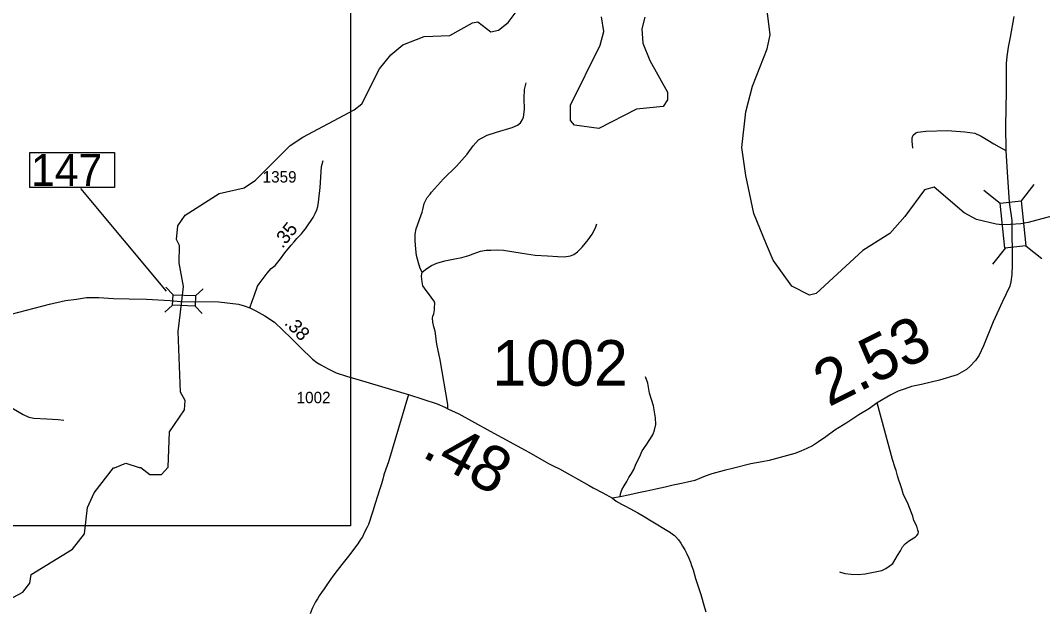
# Model space of a CAD drawing. Extents: x 2290615 to 2522933, y 819489 to 1012715.
# Drawn here: x 2317110 to 2328328, y 910143 to 916604 of the extents above; entities that cross this region are included whole.
import ezdxf

# ---------------------------------------------------------------- set-up
doc = ezdxf.new("R2010")
doc.units = 0
for name, color, linetype in [('Exist Hydrographic Creek Single Shore', 7, 'Continuous'), ('Exist Road Non-System Type 51', 7, 'Continuous'), ('Exist Road Secondary Mileage Hundredths English Label', 7, 'Continuous'), ('Exist Road Secondary Structure Standard Bridge CELL', 7, 'Continuous'), ('Exist Road Secondary Structure Standard Bridge Number Label', 7, 'Continuous'), ('Exist Road Secondary Type 51 Attributed', 7, 'Continuous'), ('Exist Road Secondary Type 51 Number Label', 7, 'Continuous'), ('Map Preparation Inset Cut Line', 7, 'Continuous')]:
    doc.layers.add(name, color=color, linetype=linetype)

msp = doc.modelspace()

# ---------------------------------------------------------------- linework, layer by layer
at = {"layer": 'Exist Hydrographic Creek Single Shore'}
for points in [[(2318130, 911698), (2318143, 911698), (2318265, 911748), (2318413, 911701), (2318430, 911701), (2318531, 911624), (2318656, 911626), (2318730, 911704), (2318745, 912092), (2318909, 912335), (2318916, 912437), (2318865, 912527), (2318841, 913193), (2318879, 913525), (2318898, 913685), (2318850, 913945), (2318856, 914135), (2318822, 914203), (2318837, 914351), (2318919, 914469), (2319292, 914705), (2319566, 914768), (2319690, 914852), (2320069, 915232), (2320210, 915323), (2320773, 915622), (2320855, 915688), (2321051, 916073), (2321174, 916226), (2321307, 916336), (2321539, 916428), (2321822, 916440), (2322070, 916578), (2322128, 916587), (2322271, 916478), (2322355, 916498), (2322462, 916581), (2322593, 916757)], [(2329032, 914619), (2328169, 914387), (2328089, 914375), (2327977, 914366), (2327884, 914361), (2327818, 914369), (2327601, 914419), (2327467, 914495), (2327139, 914774), (2327030, 914747), (2326817, 914452), (2326653, 914268), (2326354, 914082), (2325842, 913611), (2325769, 913592), (2325575, 913689), (2325372, 913973), (2325296, 914147), (2325159, 914486), (2325071, 914902), (2325027, 915209), (2325071, 915602), (2325143, 915884), (2325306, 916294), (2325337, 916446), (2325301, 916743)], [(2323961, 916639), (2323929, 916513), (2323939, 916356), (2324016, 916166), (2324211, 915816), (2324212, 915734), (2324163, 915659), (2323872, 915631), (2323457, 915417), (2323190, 915455), (2323148, 915506), (2323146, 915674), (2323472, 916334), (2323513, 916483), (2323486, 916643)], [(2313621, 908879), (2313811, 909041), (2314523, 909421), (2314895, 909686), (2315202, 909908), (2315283, 909951), (2315463, 910033), (2315820, 910031), (2315981, 909789), (2316170, 909673), (2316626, 909803), (2316700, 909878), (2316790, 910095), (2316864, 910190), (2317137, 910333), (2317211, 910434), (2317227, 910527), (2317682, 910805), (2317813, 910974), (2317844, 911264), (2317917, 911425), (2318130, 911698)]]:
    msp.add_lwpolyline(points, dxfattribs=at)
at = {"layer": 'Exist Road Non-System Type 51'}
for points in [[(2321517, 913844), (2321496, 913883), (2321477, 913944), (2321457, 914027), (2321450, 914096), (2321442, 914190), (2321441, 914261), (2321454, 914317), (2321505, 914460), (2321517, 914500), (2321525, 914529), (2321541, 914595), (2321574, 914661), (2321605, 914698), (2321621, 914722), (2321753, 914866), (2321897, 915004), (2322011, 915138), (2322078, 915229), (2322138, 915294), (2322168, 915312), (2322231, 915347), (2322334, 915380), (2322505, 915431), (2322564, 915456), (2322596, 915481), (2322619, 915517), (2322629, 915543), (2322640, 915627), (2322637, 915752), (2322643, 915845), (2322659, 915918)], [(2326903, 915203), (2326898, 915281), (2326898, 915315), (2326909, 915345), (2326935, 915370), (2326957, 915380), (2327047, 915391), (2327283, 915397), (2327475, 915381), (2327583, 915368), (2327654, 915333), (2327727, 915290), (2327792, 915250), (2327853, 915217), (2327924, 915177)], [(2326903, 915203), (2326898, 915281), (2326898, 915315), (2326909, 915345), (2326935, 915370), (2326957, 915380), (2327047, 915391), (2327283, 915397), (2327475, 915381), (2327583, 915368), (2327654, 915333), (2327727, 915290), (2327792, 915250), (2327853, 915217), (2327924, 915177)], [(2321517, 913844), (2321571, 913885), (2321621, 913917), (2321680, 913941), (2321768, 913968), (2321876, 913988), (2321955, 914004), (2322029, 914025), (2322079, 914046), (2322157, 914072), (2322220, 914083), (2322274, 914086), (2322348, 914087), (2322412, 914083), (2322615, 914052), (2322759, 914031), (2322893, 914021), (2323009, 914014), (2323077, 914013), (2323145, 914023), (2323183, 914038), (2323224, 914066), (2323276, 914119), (2323341, 914197), (2323386, 914260), (2323421, 914330), (2323437, 914374)], [(2321517, 913844), (2321571, 913885), (2321621, 913917), (2321680, 913941), (2321768, 913968), (2321876, 913988), (2321955, 914004), (2322029, 914025), (2322079, 914046), (2322157, 914072), (2322220, 914083), (2322274, 914086), (2322348, 914087), (2322412, 914083), (2322615, 914052), (2322759, 914031), (2322893, 914021), (2323009, 914014), (2323077, 914013), (2323145, 914023), (2323183, 914038), (2323224, 914066), (2323276, 914119), (2323341, 914197), (2323386, 914260), (2323421, 914330), (2323437, 914374)], [(2321801, 912346), (2321801, 912393), (2321717, 912880), (2321679, 913052), (2321663, 913195), (2321646, 913245), (2321635, 913294), (2321632, 913338), (2321636, 913359), (2321647, 913387), (2321654, 913431), (2321655, 913469), (2321657, 913484), (2321656, 913505), (2321649, 913525), (2321636, 913542), (2321600, 913593), (2321572, 913626), (2321543, 913666), (2321527, 913694), (2321523, 913714), (2321517, 913736), (2321514, 913768), (2321513, 913802), (2321517, 913844)], [(2323693, 911381), (2323694, 911411), (2323702, 911435), (2323710, 911457), (2323737, 911501), (2323763, 911549), (2323788, 911590), (2323816, 911636), (2323841, 911678), (2323869, 911746), (2323904, 911815), (2323932, 911884), (2323976, 911946), (2324049, 912061), (2324069, 912112), (2324082, 912172), (2324079, 912244), (2324058, 912378), (2324015, 912516), (2323994, 912625), (2323969, 912697)], [(2316967, 912383), (2317034, 912345), (2317140, 912284), (2317203, 912252), (2317257, 912243), (2317400, 912236), (2317525, 912227), (2317586, 912220)], [(2326099, 910555), (2326159, 910538), (2326226, 910531), (2326304, 910529), (2326382, 910534), (2326565, 910572), (2326608, 910592), (2326644, 910618), (2326684, 910649), (2326711, 910691), (2326736, 910735), (2326767, 910787), (2326791, 910831), (2326820, 910863), (2326855, 910892), (2326887, 910913), (2326916, 910929), (2326933, 910942), (2326948, 910956), (2326963, 910972), (2326964, 910978), (2326965, 910993), (2326960, 911012), (2326946, 911056), (2326916, 911121), (2326902, 911168), (2326888, 911205), (2326871, 911253), (2326854, 911298), (2326829, 911347), (2326803, 911402), (2326782, 911467), (2326764, 911522), (2326751, 911563), (2326736, 911611), (2326721, 911669), (2326715, 911687), (2326708, 911710), (2326679, 911787), (2326512, 912412)]]:
    msp.add_lwpolyline(points, dxfattribs=at)
at = {"layer": 'Exist Road Secondary Structure Standard Bridge CELL'}
for p, q in [((2327684, 914743), (2327861, 914601)), ((2328233, 914803), (2328091, 914626)), ((2327919, 914109), (2327777, 913932)), ((2328144, 914133), (2328320, 913992)), ((2318707, 913680), (2318784, 913596)), ((2319031, 913585), (2319115, 913662)), ((2318696, 913404), (2318779, 913481)), ((2319027, 913472), (2319103, 913389))]:
    msp.add_line(p, q, dxfattribs=at)
for points in [[(2328091, 914626), (2328145, 914133), (2327915, 914108), (2327861, 914601)], [(2318784, 913596), (2319031, 913586), (2319026, 913470), (2318779, 913481)]]:
    msp.add_lwpolyline(points, close=True, dxfattribs=at)
at = {"layer": 'Exist Road Secondary Structure Standard Bridge Number Label'}
msp.add_line((2318712, 913634), (2317772, 914762), dxfattribs=at)
msp.add_lwpolyline([(2317214, 915154), (2318143, 915154), (2318143, 914770), (2317214, 914770)], close=True, dxfattribs=at)
at = {"layer": 'Exist Road Secondary Type 51 Attributed'}
for points in [[(2328014, 916646), (2327971, 916421), (2327951, 916309), (2327937, 916207), (2327928, 916130), (2327928, 915828), (2327920, 915446), (2327924, 915177), (2327938, 914938), (2327962, 914610), (2327991, 914408)], [(2319626, 913453), (2319654, 913524), (2319674, 913583), (2319713, 913688), (2319731, 913716), (2319772, 913773), (2319816, 913832), (2319863, 913882), (2319907, 913918), (2319962, 913989), (2320013, 914055), (2320080, 914138), (2320115, 914177), (2320143, 914211), (2320166, 914235), (2320195, 914265), (2320216, 914294), (2320237, 914320), (2320268, 914363), (2320301, 914411), (2320324, 914443), (2320344, 914486), (2320362, 914527), (2320372, 914565), (2320381, 914609), (2320386, 914645), (2320398, 914773), (2320414, 915002), (2320431, 915066)], [(2327991, 914408), (2327995, 913922), (2327991, 913817), (2327981, 913737), (2327967, 913688), (2327888, 913521), (2327784, 913298), (2327679, 913034), (2327630, 912934), (2327591, 912874), (2327531, 912807), (2327492, 912775), (2327391, 912718), (2327196, 912657), (2326999, 912612), (2326889, 912588), (2326820, 912565), (2326743, 912538), (2326662, 912498), (2326512, 912412), (2326428, 912347), (2326312, 912280), (2326189, 912199), (2326049, 912110), (2325949, 912038), (2325870, 911984), (2325803, 911939), (2325742, 911908), (2325675, 911880), (2325608, 911854), (2325326, 911778), (2325249, 911762), (2325127, 911742), (2324926, 911689), (2324833, 911669), (2324699, 911632), (2324624, 911606), (2324579, 911588), (2324512, 911558), (2324432, 911541), (2324363, 911526), (2324273, 911507), (2324187, 911486), (2324082, 911463), (2323986, 911440), (2323894, 911423), (2323798, 911400), (2323693, 911381), (2323607, 911364)], [(2316924, 913361), (2317427, 913494), (2317604, 913533), (2317723, 913548), (2317836, 913564), (2317971, 913564), (2318131, 913555), (2318304, 913549), (2318493, 913547), (2318754, 913531)], [(2318754, 913531), (2318868, 913523), (2319287, 913516), (2319502, 913493), (2319564, 913475), (2319626, 913453)], [(2319626, 913453), (2319692, 913419), (2319793, 913365), (2319899, 913294), (2320081, 913121), (2320182, 913016), (2320315, 912890), (2320363, 912853), (2320408, 912826), (2320487, 912783), (2320576, 912740), (2320687, 912701), (2320901, 912639), (2321319, 912517), (2321367, 912500)], [(2321367, 912500), (2321149, 911764), (2321120, 911684), (2321099, 911619), (2321088, 911573), (2321074, 911521), (2321051, 911457), (2321030, 911386), (2321001, 911306), (2320976, 911223), (2320960, 911166), (2320944, 911120), (2320928, 911076), (2320913, 911039), (2320891, 910999), (2320863, 910939), (2320842, 910911), (2320813, 910864), (2320776, 910817), (2320734, 910760), (2320694, 910709), (2320638, 910638), (2320587, 910571), (2320537, 910508), (2320486, 910436), (2320444, 910370), (2320412, 910329), (2320389, 910295), (2320369, 910259), (2320349, 910228), (2320333, 910199), (2320320, 910170), (2320310, 910153), (2320288, 910098)], [(2321367, 912500), (2321683, 912399), (2321766, 912361), (2321801, 912346), (2321920, 912291), (2322264, 912098), (2322690, 911869), (2322905, 911745), (2322957, 911721), (2323024, 911685), (2323351, 911505), (2323396, 911478), (2323500, 911423), (2323607, 911364)], [(2323607, 911364), (2323647, 911330), (2323708, 911299), (2323744, 911281), (2323796, 911252), (2323886, 911203), (2323955, 911164), (2324013, 911128), (2324243, 910987), (2324265, 910971), (2324283, 910959), (2324303, 910942), (2324331, 910908), (2324356, 910872), (2324376, 910838), (2324401, 910797), (2324425, 910753), (2324445, 910707), (2324464, 910663), (2324476, 910626), (2324493, 910578), (2324520, 910482), (2324576, 910307), (2324617, 910167), (2324632, 910119)]]:
    msp.add_lwpolyline(points, dxfattribs=at)
at = {"layer": 'Map Preparation Inset Cut Line'}
msp.add_lwpolyline([(2310882, 920163), (2320733, 920163), (2320733, 911061), (2310882, 911061)], close=True, dxfattribs=at)

# ---------------------------------------------------------------- texts
at = {"layer": 'Exist Road Secondary Mileage Hundredths English Label'}
for s, height, rotation, p in [('.35', 150, 51.1802, (2319986, 914096)), ('.38', 150, 314.0697, (2319998, 913278)), ('2.53', 500, 26.5822, (2325981, 912361)), ('.48', 500, 331.7308, (2321500, 911827))]:
    msp.add_text(s, height=height, rotation=rotation, dxfattribs=at).set_placement(p)
at = {"layer": 'Exist Road Secondary Structure Standard Bridge Number Label'}
msp.add_text('147', height=350, dxfattribs=at).set_placement((2317226, 914789))
at = {"layer": 'Exist Road Secondary Type 51 Number Label'}
for s, height, p in [('1359', 125, (2319768, 914826)), ('1002', 500, (2322288, 912598)), ('1002', 125, (2320141, 912406))]:
    msp.add_text(s, height=height, rotation=360, dxfattribs=at).set_placement(p)

doc.saveas('drawing.dxf')
